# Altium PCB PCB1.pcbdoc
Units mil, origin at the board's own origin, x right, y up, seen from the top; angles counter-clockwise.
Board outline 4319.97 x 3807.09 mil, 2 copper layers (Top Layer, Bottom Layer); 37 components, 97 nets, 317 pads, 179 vias.
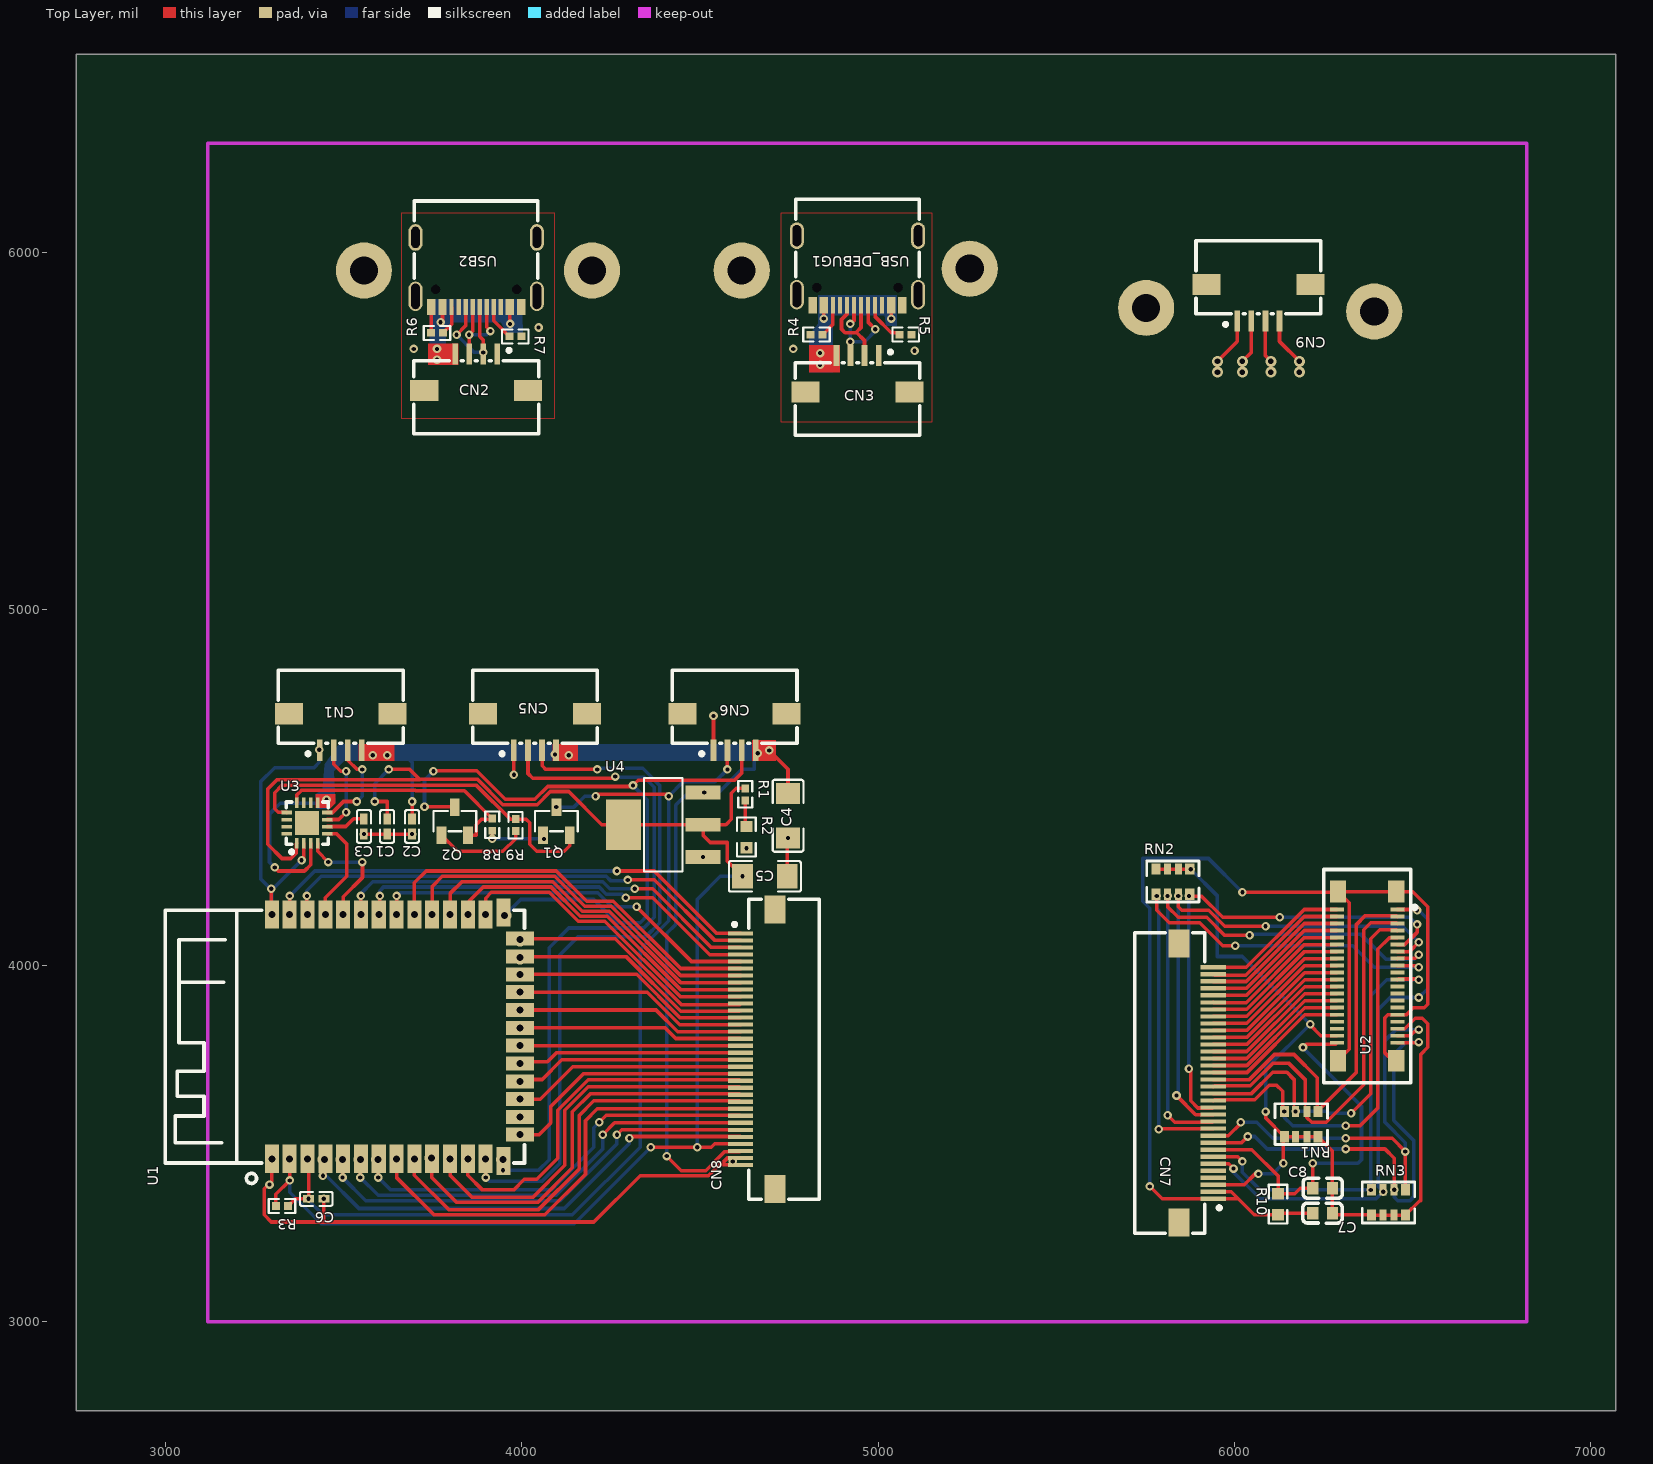
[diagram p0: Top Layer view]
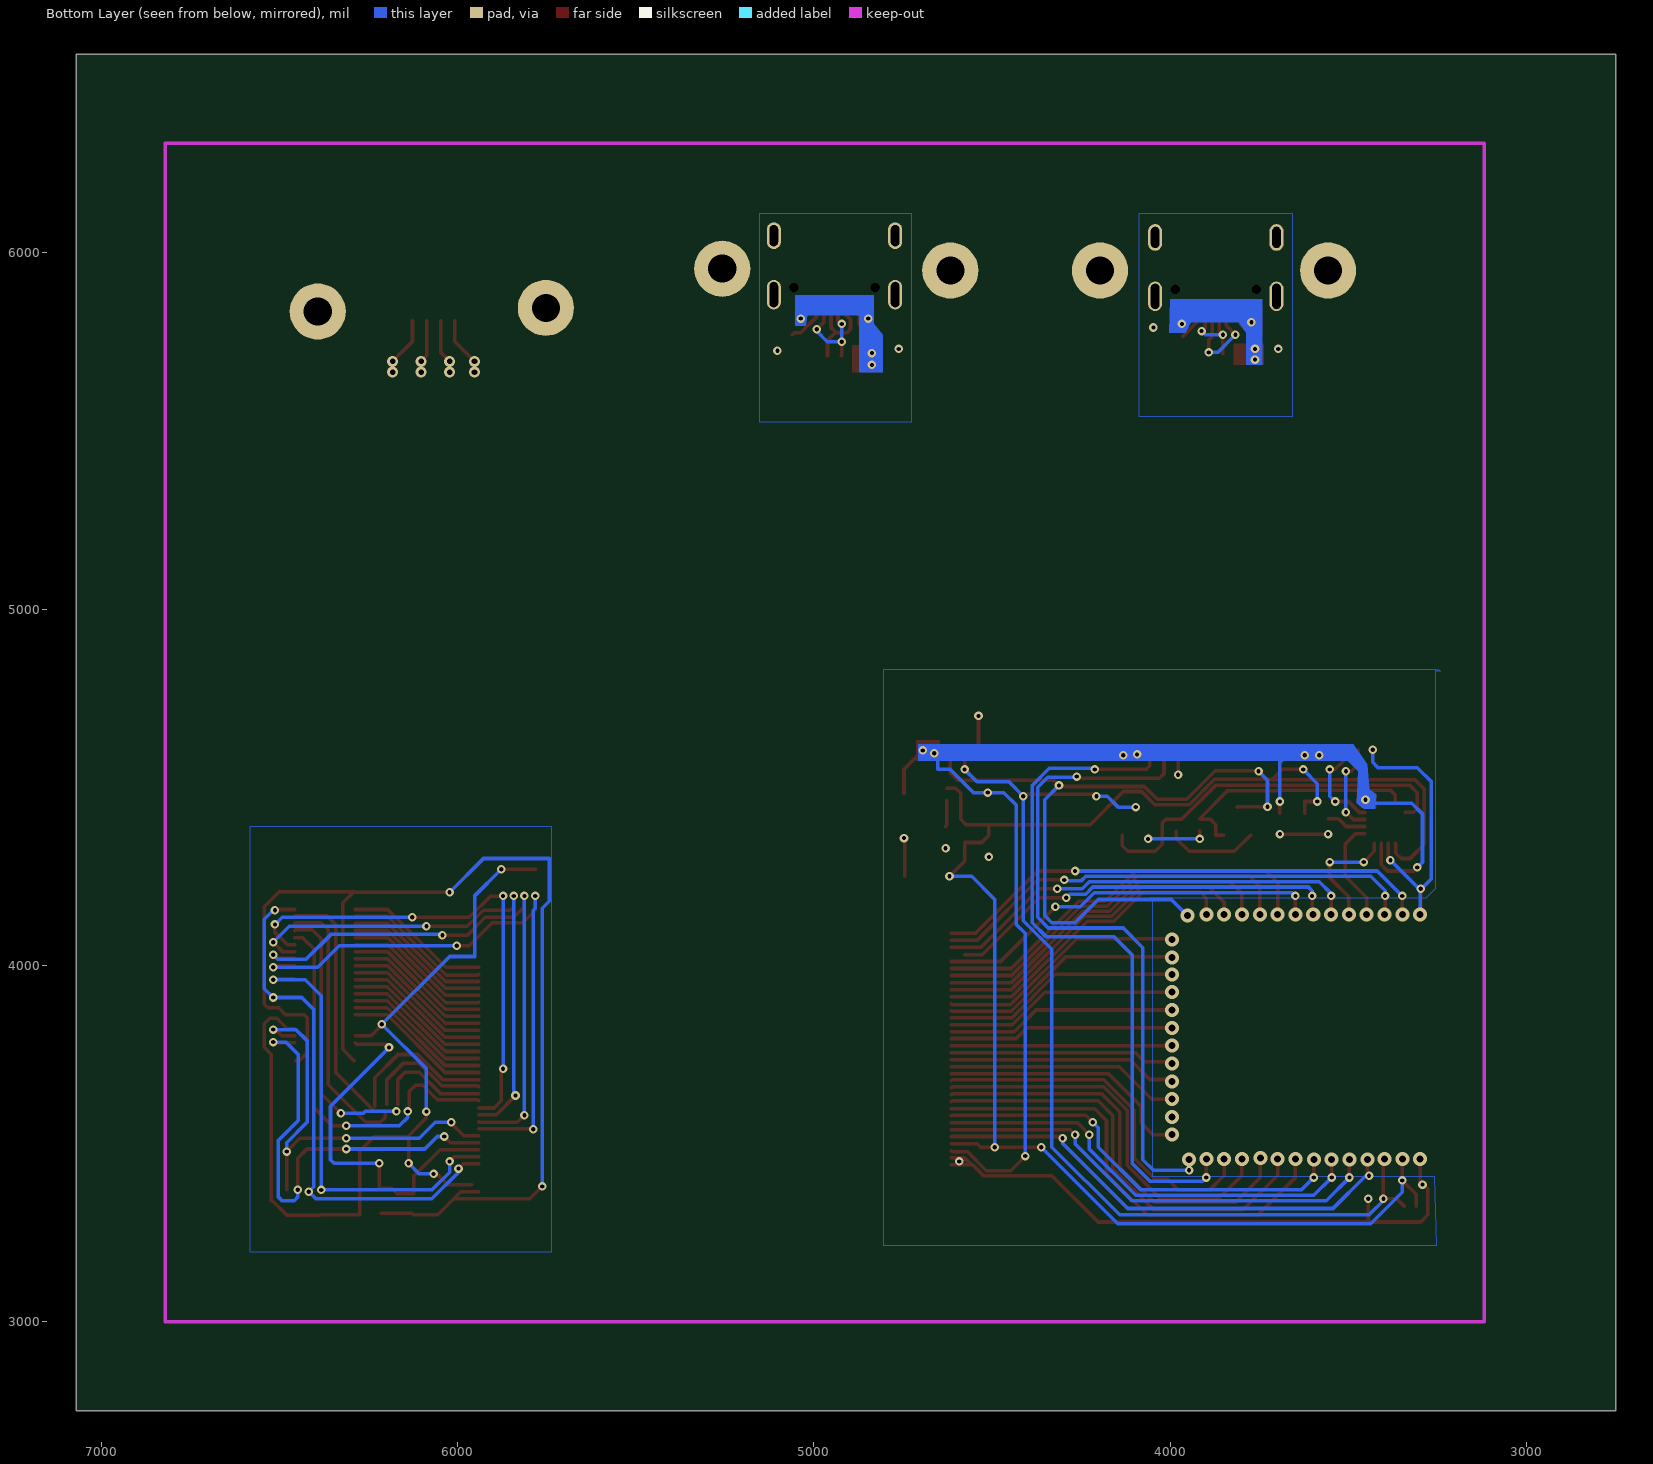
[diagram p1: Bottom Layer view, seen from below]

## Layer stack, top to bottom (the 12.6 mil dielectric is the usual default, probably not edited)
Top Layer: signal copper (thickness not stored)
Dielectric: dielectric 12.6, FR-4, Dk 4.8
Bottom Layer: signal copper (thickness not stored)

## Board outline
7069.97,2750 2750,2750 2750,6557.09 7069.97,6557.09

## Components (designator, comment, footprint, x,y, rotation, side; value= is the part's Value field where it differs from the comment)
C1 "CL05A105KA5NQNC" C0402 3622.3,4390.24 r270 top
C2 "CL05A105KA5NQNC" C0402 3692.3,4390.24 r90 top
C3 "CL05B104KO5NNNC" C0402 3557.3,4390.24 r90 top
C4 "CL31A106KBHNNNE" C1206 4747.3,4420.24 r90 top
C5 "C3216X5R1V226MTJ00E" C1206 4682.3,4250.24 r180 top
C6 "CL05A105KP5NNNC" C0402 3423.46,3345.24 r180 top
C7 "CL10A225KO8NNNC" C0603 6247.3,3375.24 r180 top
C8 "0603B104K500NT" C0603 6247.3,3305.24 r0 top
CN1 "KH-FG1.0-H2.0-4PIN" FPC-SMD_KH-FG1.0-H2.0-4PIN 3492.3,4655.24 r180 top
CN2 "KH-FG1.0-H2.0-4PIN" FPC-SMD_KH-FG1.0-H2.0-4PIN 3872.3,5665.24 r0 top
CN3 "KH-FG1.0-H2.0-4PIN" FPC-SMD_KH-FG1.0-H2.0-4PIN 4942.3,5660.24 r0 top
CN5 "KH-FG1.0-H2.0-4PIN" FPC-SMD_KH-FG1.0-H2.0-4PIN 4037.3,4655.24 r180 top
CN6 "KH-FG1.0-H2.0-4PIN" FPC-SMD_KH-FG1.0-H2.0-4PIN 4597.3,4655.24 r180 top
CN7 "KH-FG0.5-H2.0-34PIN" FPC-SMD_KH-FG0.5-H2.0-34PIN 5892.3,3670.24 r270 top
CN8 "KH-FG0.5-H2.0-34PIN" FPC-SMD_KH-FG0.5-H2.0-34PIN 4662.3,3765.24 r90 top
CN9 "KH-FG1.0-H2.0-4PIN" FPC-SMD_KH-FG1.0-H2.0-4PIN 6067.3,5860.24 r180 top
Q1 "SS8050G-Y1" SOT-23-3_L2.9-W1.3-P1.90-LS2.4-BR 4097.3,4405.24 r270 top
Q2 "SS8050G-Y1" SOT-23-3_L2.9-W1.3-P1.90-LS2.4-BR 3812.3,4405.24 r270 top
R1 "0402WGF6800TCE" R0402 4627.3,4480.24 r270 top
R2 "0603WAF0000T5E" R0603 4630.56,4360.43 r270 top
R3 "0402WGF1002TCE" R0402 3327.3,3325.24 r180 top
R4 "0402WGF5101TCE" R0402 4827.3,5770.24 r180 top
R5 "0402WGF5101TCE" R0402 5077.3,5770.24 r0 top
R6 "0402WGF5101TCE" R0402 3762.3,5775.24 r180 top
R7 "0402WGF5101TCE" R0402 3982.3,5765.24 r0 top
R8 "0402WGF1002TCE" R0402 3917.3,4395.24 r270 top
R9 "0402WGF1002TCE" R0402 3983.06,4393.97 r270 top
R10 "0603WAF1003T5E" R0603 6122.3,3330.24 r270 top
RN1 "4D03WGJ0472T5E" RES-ARRAY-SMD_0603-8P-L3.2-W1.6-BL 6187.3,3555.24 r180 top
RN2 "4D03WGJ0472T5E" RES-ARRAY-SMD_0603-8P-L3.2-W1.6-BL 5827.3,4235.24 r0 top
RN3 "4D03WGJ0472T5E" RES-ARRAY-SMD_0603-8P-L3.2-W1.6-BL 6432.3,3335.24 r180 top
U1 "ESP-S3-32S" WIFIM-SMD_40P-L25.5-W18.0-P1.27-TL 3647.3,3800.24 r90 top
U2 "AA01B-S040VA1" CONN-SMD_AA01B-S040VA1 6372.3,3970.24 r90 top
U3 "CH343P" TQFN-16_L3.0-W3.0-P0.50-BL-EP1.7 3397.94,4399.85 r0 top
U4 "AMS1117-3.3_C347222" SOT-223-4_L6.5-W3.5-P2.30-LS7.0-BR 4397.3,4395.24 r0 top
USB2 "TYPEC-304J-BCP16" USB-C-SMD_TYPEC-304J-BCP16 3872.3,5945.24 r180 top
USB_DEBUG1 "TYPEC-304J-BCP16" USB-C-SMD_TYPEC-304J-BCP16 4942.3,5950.24 r180 top

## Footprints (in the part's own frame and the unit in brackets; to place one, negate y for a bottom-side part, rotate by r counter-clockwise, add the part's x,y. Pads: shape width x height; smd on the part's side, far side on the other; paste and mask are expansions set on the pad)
C0402 [mm]
  rect 0.79x0.54 smd paste-100 mask+0.051: 1(-0.545,0) 2(0.545,0)
  silkscreen extent -1.17,-0.5 1.17,0.5
C0603 [mm]
  rect 0.8x0.9 smd paste+0 mask+0.051: 1(-0.7,0) 2(0.7,0)
  silkscreen extent -1.41,-0.71 1.39,0.72
C1206 [mm]
  rect 1.485x1.728 smd paste-100 mask+0.051: 1(-1.593,0) 2(1.593,0)
  silkscreen extent -2.56,-1.09 2.56,1.09
CONN-SMD_AA01B-S040VA1 [mm]
  rect 0.28x1 smd paste+0 mask+0.051: 1(4.75,-2.158) 2(4.75,2.158) 3(4.25,-2.158) 4(4.25,2.158) 5(3.75,-2.158) 6(3.75,2.158) 7(3.25,-2.158) 8(3.25,2.158) 9(2.75,-2.158) 10(2.75,2.158) 11(2.25,-2.158) 12(2.25,2.158) 13(1.75,-2.158) 14(1.75,2.158) 15(1.25,-2.158) 16(1.25,2.158) 17(0.75,-2.158) 18(0.75,2.158) 19(0.249,-2.158) 20(0.249,2.158) 21(-0.25,-2.158) 22(-0.25,2.158) 23(-0.75,-2.158) 24(-0.75,2.158) 25(-1.25,-2.158) 26(-1.25,2.158) 27(-1.75,-2.158) 28(-1.75,2.158) 29(-2.25,-2.158) 30(-2.25,2.158) 31(-2.75,-2.158) 32(-2.75,2.158) 33(-3.25,-2.158) 34(-3.25,2.158) 35(-3.75,-2.158) 36(-3.75,2.158) 37(-4.25,-2.158) 38(-4.25,2.158) 39(-4.75,-2.158) 40(-4.75,2.158)
  rect 1.55x1.15 smd paste+0 mask+0.051: 41(6.025,2.075) 42(6.025,-2.075) 43(-6.025,2.075) 44(-6.025,-2.075)
  silkscreen extent -7.6,-3.54 7.6,3.1
FPC-SMD_KH-FG0.5-H2.0-34PIN [mm]
  rect 0.3x1.8 smd paste+0 mask+0.051: 1(8.25,1.225) 2(7.75,1.225) 3(7.25,1.225) 4(6.75,1.225) 5(6.25,1.225) 6(5.75,1.225) 7(5.25,1.225) 8(4.75,1.225) 9(4.25,1.225) 10(3.75,1.225) 11(3.25,1.225) 12(2.75,1.225) 13(2.25,1.225) 14(1.75,1.225) 15(1.25,1.225) 16(0.75,1.225) 17(0.25,1.225) 18(-0.25,1.225) 19(-0.75,1.225) 20(-1.25,1.225) 21(-1.75,1.225) 22(-2.25,1.225) 23(-2.75,1.225) 24(-3.25,1.225) 25(-3.75,1.225) 26(-4.25,1.225) 27(-4.75,1.225) 28(-5.25,1.225) 29(-5.75,1.225) 30(-6.25,1.225) 31(-6.75,1.225) 32(-7.25,1.225) 33(-7.75,1.225) 34(-8.25,1.225)
  rect 2x1.5 smd paste+0 mask+0.051: 35(-9.95,-1.225) 36(9.95,-1.225)
  silkscreen extent -10.7,-4.38 10.7,1.78
FPC-SMD_KH-FG1.0-H2.0-4PIN [mm]
  rect 0.4x1.5 smd paste+0 mask+0.05: 1(1.5,1.3) 2(0.5,1.3) 3(-0.5,1.3) 4(-1.5,1.3)
  rect 2x1.5 smd paste+0 mask+0.05: 5(-3.7,-1.3) 6(3.7,-1.3)
  silkscreen extent -4.45,-4.39 4.45,1.68
R0402 [mm]
  rect 0.566x0.54 smd paste-100 mask+0.051: 1(-0.433,0) 2(0.433,0)
  silkscreen extent -0.94,-0.5 0.94,0.5
R0603 [mil]
  rect 31.75x34.02 smd paste-3937.01 mask+2: 1(-29.66,0) 2(29.66,0)
  silkscreen extent -55,-26 55,26
RES-ARRAY-SMD_0603-8P-L3.2-W1.6-BL [mm]
  rect 0.65x0.8 smd paste+0 mask+0.051: 1(-1.2,-0.9) 4(1.2,-0.9) 5(1.2,0.9) 8(-1.2,0.9)
  rect 0.5x0.8 smd paste+0 mask+0.051: 2(-0.4,-0.9) 3(0.4,-0.9) 6(0.4,0.9) 7(-0.4,0.9)
  silkscreen extent -1.87,-1.45 1.87,1.47
SOT-23-3_L2.9-W1.3-P1.90-LS2.4-BR [mm]
  rect 1.25x0.7 smd paste+0 mask+0.051: 1(1,-0.95) 2(1,0.95) 3(-1,0)
  silkscreen extent -0.73,-1.53 0.73,1.53
SOT-223-4_L6.5-W3.5-P2.30-LS7.0-BR [mm]
  rect 2.47x0.98 smd paste+0 mask+0.051: 1(2.835,-2.3) 2(2.835,0) 3(2.835,2.3)
  rect 2.47x3.6 smd paste+0 mask+0.051: 4(-2.835,0)
  silkscreen extent -1.37,-3.33 1.37,3.33
TQFN-16_L3.0-W3.0-P0.50-BL-EP1.7 [mm]
  rect 0.25x0.75 smd paste-100 mask+0.051: 1(-0.748,-1.45) 2(-0.249,-1.45) 3(0.252,-1.45) 4(0.751,-1.45) 9(0.75,1.45) 10(0.25,1.45) 11(-0.25,1.45) 12(-0.749,1.45)
  rect 0.75x0.25 smd paste-100 mask+0.051: 5(1.45,-0.75) 6(1.45,-0.25) 7(1.45,0.25) 8(1.45,0.75) 13(-1.45,0.75) 14(-1.45,0.25) 15(-1.45,-0.25) 16(-1.45,-0.75)
  rect 1.7x1.7 smd paste-100 mask+0.051: 17(0,0)
  silkscreen extent -1.5,-2.17 1.5,1.5
USB-C-SMD_TYPEC-304J-BCP16 [mm]
  oval 1x2.1 hole 0.6 slot 1.8 at 90 deg paste+0 mask+0.051: 13(-4.325,1.719) 14(4.325,1.719)
  oval 1x1.9 hole 0.6 slot 1.5 at 90 deg paste+0 mask+0.051: 15(-4.325,-2.481) 16(4.325,-2.481)
  rect 0.6x1.15 smd paste-100 mask+0.051: A1B12(-3.2,2.481) A4B9(-2.4,2.481) B1A12(3.2,2.481) B4A9(2.4,2.481)
  rect 0.3x1.15 smd paste-100 mask+0.051: A5(-1.25,2.481) A6(-0.25,2.481) A7(0.25,2.481) A8(1.25,2.481) B5(1.75,2.481) B6(0.75,2.481) B7(-0.75,2.481) B8(-1.75,2.481)
  Multi-Layer board cut-out: 2.565,1.219 2.597,1.078 2.688,0.965 2.818,0.902 2.962,0.902 3.093,0.965 3.183,1.078 3.215,1.219 3.215,1.219 3.183,1.36 3.093,1.473 2.962,1.536 2.818,1.536 2.688,1.473 2.597,1.36 2.565,1.219
  Multi-Layer board cut-out: -3.215,1.219 -3.183,1.078 -3.093,0.965 -2.962,0.902 -2.818,0.902 -2.687,0.965 -2.597,1.078 -2.565,1.219 -2.565,1.219 -2.597,1.36 -2.687,1.473 -2.818,1.536 -2.962,1.536 -3.093,1.473 -3.183,1.36 -3.215,1.219
  silkscreen extent -4.4,-5.08 4.4,0.44
WIFIM-SMD_40P-L25.5-W18.0-P1.27-TL [mm]
  rect 2x1 smd paste+0 mask+0.051: 1(-8.7,8.849) 2(-8.7,7.579) 3(-8.7,6.309) 4(-8.7,5.039) 5(-8.7,3.769) 6(-8.7,2.499) 7(-8.7,1.229) 8(-8.7,-0.041) 9(-8.7,-1.311) 10(-8.7,-2.581) 11(-8.7,-3.851) 12(-8.7,-5.121) 13(-8.7,-6.391) 14(-8.85,-7.661) 27(8.85,-7.661) 28(8.7,-6.391) 29(8.7,-5.121) 30(8.7,-3.851) 31(8.7,-2.581) 32(8.7,-1.311) 33(8.7,-0.041) 34(8.7,1.229) 35(8.7,2.499) 36(8.7,3.769) 37(8.7,5.039) 38(8.7,6.309) 39(8.7,7.579) 40(8.7,8.849)
  rect 1x2 smd paste+0 mask+0.051: 15(-6.986,-8.849) 16(-5.716,-8.849) 17(-4.446,-8.849) 18(-3.176,-8.849) 19(-1.906,-8.849) 20(-0.636,-8.849) 21(0.634,-8.849) 22(1.904,-8.849) 23(3.174,-8.849) 24(4.444,-8.849) 25(5.714,-8.849) 26(6.984,-8.849)
  silkscreen extent -10.46,-9.16 9,16.44

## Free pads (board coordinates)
  round 157.48 hole 78.74 paste+0 mask+2: 1(3557.3,5950.24) 1(4197.3,5950.24) 1(4617.3,5950.24) 1(5257.3,5955.24) 1(5752.3,5845.24) 1(6392.3,5835.24)

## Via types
v1: diameter 24.02, hole 12.01, Top Layer to Bottom Layer, 131 vias
v2: diameter 39.37, hole 19.68, Top Layer to Bottom Layer, 40 vias
v3: diameter 31.5, hole 15.75, Top Layer to Bottom Layer, 8 vias

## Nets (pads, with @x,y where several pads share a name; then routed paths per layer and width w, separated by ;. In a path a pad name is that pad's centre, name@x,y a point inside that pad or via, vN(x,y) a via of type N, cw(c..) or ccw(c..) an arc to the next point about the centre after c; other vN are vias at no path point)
$1N3962: R1.2 R2.1 | length 74.5
  Top Layer w10: R1.2 4627.3,4393.35 R2.1
$1N4727: R5.1 USB_DEBUG1.A5 | length 121.3
  Top Layer w10: USB_DEBUG1.A5 4991.5,5821.03 5037.3,5775.24 5055.26,5775.24 R5.1
$1N4742: R4.1 USB_DEBUG1.B5 | length 94.3
  Top Layer w10: R4.1 4873.4,5799.3 USB_DEBUG1.B5
$1N5488: R7.1 USB2.A5 | length 100.4
  Top Layer w10: USB2.A5 3921.5,5808.99 R7.1
$1N5500: R6.1 USB2.B5 | length 82.3
  Top Layer w10: R6.1 3803.4,5799.3 USB2.B5
$1N6780: Q2.1 R9.2 | length 262.8
  Top Layer w10: Q2.1 3820.53,4320.24 3947.3,4320.24 3983.06,4356.01 R9.2
$1N6783: Q1.1 R8.2 | length 179.6
  Top Layer w10: v1(3917.3,4355.24) R8.2 ; Q1.1 4062.3,4363.47 v1(4062.3,4355.24)
  Bottom Layer w10: v1(3917.3,4355.24) v1(4062.3,4355.24)
$1N7702: CN7.34 U2.2 | length 414
  Top Layer w10: CN7.34 6033.46,3995.04 6195.66,4157.24 U2.2
$1N7716: CN7.33 U2.4 | length 415.8
  Top Layer w10: CN7.33 5942.72,3973.15 6031.37,3973.15 6195.77,4137.55 U2.4
$1N7875: CN7.32 U2.6 | length 414.4
  Top Layer w10: CN7.32 5940.95,3955.24 6033.26,3955.24 6195.88,4117.86 U2.6
$1N7880: CN7.31 U2.8 | length 414
  Top Layer w10: CN7.31 6033.8,3935.98 6196,4098.18 U2.8
$1N7885: CN7.30 U2.10 | length 414
  Top Layer w10: CN7.30 6033.91,3916.3 6196.11,4078.49 U2.10
$1N7890: CN7.29 U2.12 | length 415.1
  Top Layer w10: CN7.29 5941.89,3895.24 6032.65,3895.24 6196.22,4058.81 U2.12
$1N7895: CN7.28 U2.14 | length 414
  Top Layer w10: CN7.28 6034.14,3876.93 6196.33,4039.12 U2.14
$1N7900: CN7.27 U2.16 | length 414
  Top Layer w10: CN7.27 6034.25,3857.24 6196.45,4019.44 U2.16
$1N7909: CN7.26 U2.18 | length 414
  Top Layer w10: CN7.26 6034.37,3837.56 6196.56,3999.75 U2.18
$1N7914: CN7.25 U2.20 | length 414
  Top Layer w10: CN7.25 6034.48,3817.87 6196.67,3980.06 U2.20
$1N7919: CN7.24 U2.22 | length 414
  Top Layer w10: CN7.24 6034.6,3798.19 6196.79,3960.38 U2.22
$1N7924: CN7.23 U2.24 | length 414
  Top Layer w10: CN7.23 6034.71,3778.5 6196.91,3940.7 U2.24
$1N7938: CN7.22 U2.26 | length 414
  Top Layer w10: CN7.22 6034.83,3758.82 6197.02,3921.01 U2.26
$1N7945: CN7.21 U2.28 | length 414
  Top Layer w10: CN7.21 6034.94,3739.13 6197.14,3901.33 U2.28
$1N7952: CN7.20 U2.30 | length 414
  Top Layer w10: CN7.20 6035.05,3719.45 6197.25,3881.64 U2.30
$1N7980: CN7.19 U2.32 | length 414
  Top Layer w10: CN7.19 6035.16,3699.76 6197.36,3861.96 U2.32
$1N11911: CN7.18 RN1.1 U2.3 | length 1122.9
  Top Layer w10: CN7.18 6042.14,3680.08 6112.3,3750.24 6167.3,3750.24 6232.3,3685.24 RN1.1@6232.3,3605.67 ; RN1.1 6234.53,3592.48 6342.3,3700.24 6342.3,4115.24 6367.3,4140.24 6454.56,4140.24 U2.3
$1N11924: CN7.17 RN1.2 U2.5 | length 1137.4
  Top Layer w10: CN7.17 5942.73,3662.6 6044.65,3662.6 6107.3,3725.24 6153.05,3725.24 6198.05,3680.24 6198.05,3610.67 ; RN1.2 6203.05,3573.66 6216.47,3560.24 6257.71,3560.24 6362.71,3665.24 6362.71,4100.65 6382.3,4120.24 6454.87,4120.24 U2.5
$1N11961: CN7.15 RN1.4 U2.9 | length 1084.2
  Top Layer w10: CN7.15 5943.32,3623.82 6056.97,3623.82 6097.3,3664.14 6117.91,3664.14 6135.06,3647 RN1.4@6135.06,3605.67 ; v1(6312.3,3550.24) 6352.3,3550.24 6402.3,3600.24 6402.3,4045.24 6435.55,4078.49 U2.9
  Bottom Layer w10: v1(6140.06,3590.67) 6140.06,3573.66 6163.48,3550.24 v1(6312.3,3550.24)
$1N12399: CN7.16 RN1.3 U2.7 | length 1086.4
  Top Layer w10: CN7.16 6047.77,3640.71 6107.3,3700.24 6147.22,3700.24 6167.22,3680.24 6167.22,3611.34 6166.55,3610.67 ; v1(6327.3,3585.24) 6382.3,3640.24 6382.3,4075.24 6407.3,4100.24 6455.19,4100.24 U2.7
  Bottom Layer w10: v1(6171.55,3590.67) 6258.55,3590.67 6263.99,3585.24 v1(6327.3,3585.24)
$1N12461: CN7.14 RN2.4 U2.11 | length 1416.3
  Top Layer w10: v1(5872.3,3710.24) 5877.3,3705.24 5877.3,3620.24 5897.3,3600.24 5939.42,3600.24 CN7.14 ; RN2.4 5874.53,4194.8 5907.73,4194.8 5967.3,4135.24 v1(6127.3,4135.24) ; U2.11 6478.3,4058.81 6512.3,4092.81 v1(6512.3,4115.24)
  Bottom Layer w10: v1(5872.3,3710.24) v1(5872.3,4195.24) ; v1(6127.3,4135.24) 6492.3,4135.24 v1(6512.3,4115.24)
$1N12469: CN7.11 RN2.1 U2.17 | length 1714.3
  Top Layer w10: v1(5782.3,4195.24) 5782.3,4155.24 5817.3,4120.24 5902.3,4120.24 5967.3,4055.24 v1(6002.3,4055.24) ; v1(5787.3,3540.24) 5789.35,3542.29 CN7.11 ; U2.17 6512.78,3999.75 v1(6517.3,3995.24)
  Bottom Layer w10: v1(5782.3,4195.24) 5782.3,4160.24 5787.3,4155.24 v1(5787.3,3540.24) ; v1(6002.3,4055.24) 6332.3,4055.24 6392.3,3995.24 v1(6517.3,3995.24)
$1N12482: CN7.13 RN2.3 U2.13 | length 1504.8
  Top Layer w10: v1(5837.3,3635.24) 5890.89,3581.65 CN7.13 ; v1(5842.3,4195.24) 5842.3,4165.24 5852.3,4155.24 5927.5,4155.24 5972.5,4110.24 v1(6087.3,4110.24) ; U2.13 6491.18,4039.12 v1(6517.3,4065.24)
  Bottom Layer w10: v1(5837.3,3635.24) 5842.3,3640.24 v1(5842.3,4195.24) ; v1(6087.3,4110.24) 6472.3,4110.24 v1(6517.3,4065.24)
$1N12495: CN7.12 RN2.2 U2.15 | length 1625
  Top Layer w10: RN2.2 5812.3,4199.05 v1(5812.3,4195.24) 5812.3,4165.24 5842.3,4135.24 5921.92,4135.24 5971.92,4085.24 v1(6042.3,4085.24) ; v1(5812.3,3580.24) 5832.3,3560.24 5938.79,3560.24 CN7.12 ; U2.15 6458.04,4020.24 6507.3,4020.24 v1(6517.3,4030.24)
  Bottom Layer w10: v1(5812.3,3580.24) v1(5812.3,4195.24) ; v1(6042.3,4085.24) 6044.3,4087.24 6355.29,4087.24 6425.29,4017.24 6504.3,4017.24 v1(6517.3,4030.24)
$1N16399: CN9.1 | length 167
  Top Layer w10: v3(5952.3,5665.24) v3(5952.3,5695.24) 6008.24,5751.18 CN9.1
$1N16400: CN9.4 | length 167
  Top Layer w10: CN9.4 6126.35,5751.18 v3(6182.3,5695.24) v3(6182.3,5665.24)
$1N16402: CN9.2 | length 154.3
  Top Layer w10: v3(6022.3,5665.24) v3(6022.3,5695.24) 6047.61,5720.55 CN9.2
$1N16404: CN9.3 | length 150.2
  Top Layer w10: CN9.3 6086.98,5710.55 v3(6102.3,5695.24) v3(6102.3,5665.24)
CHIP_PU: C6.2 CN6.2 Q1.3 R3.1 U1.3 | length 2811.9
  Top Layer w10: R3.1 3364.34,3345.24 v1(3402,3345.24) 3402,3454.63 v2(3398.92,3457.72) ; v1(4207.3,4475.24) 4212.3,4480.24 4407.3,4480.24 v1(4412.3,4475.24) ; v1(4577.3,4550.24) 4577.3,4603.74 CN6.2
  Bottom Layer w10: v1@3397.3,3345.24 3442.3,3300.24 4142.3,3300.24 4332.3,3490.24 4332.3,4045.24 4412.3,4125.24 4412.3,4475.06 4452.47,4515.24 4542.3,4515.24 v1(4577.3,4550.24) ; v1(4097.3,4444.61) 4146.66,4444.61 4177.3,4475.24 v1(4207.3,4475.24)
D1+: CN2.2 USB2.A6 USB2.B6 | length 319
  Top Layer w10: v1(3817.3,5770.24) 3842.77,5795.71 USB2.B6 ; USB2.A6 3882.3,5847.38 3882.3,5765.24 3892.3,5755.24 3892.3,5716.73 CN2.2
  Bottom Layer w10: v1(3817.3,5770.24) 3867.3,5720.24 v1(3892.3,5720.24)
D1-: CN2.3 USB2.A7 USB2.B7 | length 271.3
  Top Layer w10: CN2.3 3852.3,5716.73 v1(3852.3,5770.24) 3862.3,5780.24 3862.3,5847.39 USB2.A7 ; USB2.B7 3901.82,5790.71 v1(3912.3,5780.24)
  Bottom Layer w10: v1(3852.3,5770.24) 3902.3,5770.24 v1(3912.3,5780.24)
D2+: CN3.2 USB_DEBUG1.A6 USB_DEBUG1.B6 | length 275.4
  Top Layer w10: USB_DEBUG1.B6 4912.77,5828.16 4897.3,5812.68 4897.3,5785.89 4907.3,5775.89 4937.95,5775.89 4938.95,5776.89 ; USB_DEBUG1.A6 4952.13,5790.07 4938.95,5776.89 ; CN3.2 4961.98,5753.87 4938.95,5776.89
D2-: CN3.3 USB_DEBUG1.A7 USB_DEBUG1.B7 | length 309.2
  Top Layer w10: v1(4922.3,5750.24) 4922.3,5711.73 CN3.3 ; v1(4922.3,5800.24) 4923.15,5800.24 4932.45,5809.53 USB_DEBUG1.A7 ; USB_DEBUG1.B7 4971.82,5805.71 v1(4992.3,5785.24)
  Bottom Layer w10: v1(4922.3,5800.24) v1(4922.3,5750.24) 4962.3,5750.24 4992.3,5780.24 v1(4992.3,5785.24)
D3+: CN1.2 U3.7 | length 257.7
  Top Layer w10: U3.7 3486.76,4409.7 v1(3507.3,4430.24) ; CN1.2 3472.61,4564.92 3492.3,4545.24 v1(3507.3,4545.24)
  Bottom Layer w10: v1(3507.3,4430.24) v1(3507.3,4545.24)
D3-: CN1.3 U3.8 | length 270.1
  Top Layer w10: U3.8 3469.17,4429.38 3500.03,4460.24 v1(3537.3,4460.24) ; CN1.3 3511.98,4576.41 3538.15,4550.24 v1(3552.3,4550.24)
  Bottom Layer w10: v1(3537.3,4460.24) 3552.3,4475.24 v1(3552.3,4550.24)
D+: CN5.2 U1.14 | length 1902.7
  Top Layer w10: v1(3947.3,3425.24) v2(3947.3,3455.24) ; CN5.2 4017.61,4538.76 4031.14,4525.24 4257.3,4525.24 v1(4262.3,4530.24)
  Bottom Layer w10: v1(3947.3,3425.24) 4047.3,3425.24 4077.3,3455.24 4077.3,4050.24 4132.3,4105.24 4342.3,4105.24 4372.3,4135.24 4372.3,4500.24 4344.3,4528.23 4264.3,4528.23 v1(4262.3,4530.24)
D-: CN5.3 U1.13 | length 1972.2
  Top Layer w10: v1(3898.92,3405.24) v2(3898.92,3457.72) ; CN5.3 4056.98,4594.49 4057.3,4594.18 4057.3,4560.24 4067.3,4550.24 v1(4212.3,4550.24)
  Bottom Layer w10: v1(3898.92,3405.24) 3908.92,3395.24 4057.3,3395.24 4107.3,3445.24 4107.3,4030.24 4157.3,4080.24 4347.3,4080.24 4387.3,4120.24 4387.3,4505.24 4339.3,4553.23 4215.29,4553.23 v1(4212.3,4550.24)
DTR: Q2.2 R8.1 U3.12 | length 712.5
  Top Layer w10: U3.12 3368.45,4478.7 3380.97,4491.22 3701.31,4491.22 3702.3,4490.24 3839.34,4490.24 R8.1 3915.26,4410.24 3887.3,4410.24 3872.3,4395.24 3872.3,4365.87 Q2.2
GND: C1.2 C2.1 C3.1 C4.1 C5.1 C6.1 CN1.1 CN5.1 CN6.1 CN8.33 CN8.34 R2.2 U1.1 U1.40 U3.2 U3.17 U4.1 | length 2965.4
  Top Layer w10: v1(3297.3,4215.24) 3297.3,4144.38 v2(3298.92,4142.76) ; v2(3298.92,3457.72) 3298.92,3395.24 3277.3,3373.62 3277.3,3300.24 3297.3,3280.24 3445.71,3280.24 ; v1(3382.3,4295.24) 3388.16,4301.1 U3.2 ; v1(3444.92,3345.24) 3444.92,3281.03 3445.71,3280.24 ; v1(3557.3,4368.78) C1.2 v1(3692.3,4368.78) ; v1(3978.24,4535.24) CN5.1 ; CN6.1 v1(4538.24,4700.24) ; CN8.34 4557.6,3440.44 ; CN8.33 4577.3,3460.13 4557.6,3440.44 ; C5.1 4744.99,4355.24 v1(4747.3,4357.54) ; 3445.71,3280.24 4202.3,3280.24 4332.49,3410.44 4524.07,3410.44 4554.07,3440.44 4557.6,3440.44
  Bottom Layer w10: v2(3298.92,4142.76) v1@3298.92,4211.86 ; v1(3382.3,4295.24) v1@3298.92,4211.86 ; v1(3432.3,4605.24) 3432.3,4570.24 3417.3,4555.24 3307.3,4555.24 3267.3,4515.24 3267.3,4243.48 v1@3298.92,4211.86
  other v1: 3292.3,3385.24 4592.3,3450.24 4508.9,4304.69 4630.56,4329.13
GND_11: C8.1 CN7.1 CN7.2 R10.2 U2.31 U2.41 U2.42 U2.43 U2.44 | length 3400.9
  Top Layer w10: v1(5762.3,3380.24) 5797.1,3345.44 CN7.1 6010.52,3345.44 ; CN7.2 5990.84,3365.12 6010.52,3345.44 ; v1(6022.3,4205.24) 6288.39,4205.24 U2.41 ; C8.1@6214.06,3305.24 6126.95,3305.24 R10.2 6055.38,3300.58 6010.52,3345.44 ; U2.43 6322.3,3764.72 6322.3,4175.76 U2.41 ; U2.44 6443.98,3733.03 6422.3,3754.72 6422.3,3853.69 6430.56,3861.96 U2.31 6482.85,3861.96 6501.94,3881.05 6532.3,3881.05 6542.3,3891.05 6542.3,4165.24 6500.08,4207.45 U2.42 U2.41
  Bottom Layer w10: v1(5762.3,3380.24) 5762.3,4160.24 5742.3,4180.24 5742.3,4300.24 5927.3,4300.24 v1(6022.3,4205.24)
GND_DEBUG: CN3.1 R4.2 R5.2 USB_DEBUG1.13 USB_DEBUG1.14 USB_DEBUG1.15 USB_DEBUG1.16 USB_DEBUG1.A1B12 USB_DEBUG1.B1A12
  other v1: 5102.3,5725.24 4762.3,5730.24
GND_USB: CN2.1 R6.2 R7.2 USB2.13 USB2.14 USB2.15 USB2.16 USB2.A1B12 USB2.B1A12 | length 72.7
  Top Layer w10: R6.2 3746.31,5776.29 USB2.B1A12
  other v1: 3697.3,5730.24 4047.3,5790.24
GPIO0(BOOT): CN6.3 Q2.3 U1.27 | length 2023.9
  Top Layer w10: v1(3727.3,4445.24) 3811.66,4445.24 Q2.3 ; v1(3752.3,4545.24) 3753.3,4546.24 3873.91,4546.24 3953.91,4466.24 4036.66,4466.24 4072.66,4502.24 4309.3,4502.24 v1(4312.3,4505.24) 4327.3,4520.24 4597.3,4520.24 4616.98,4539.92 CN6.3
  Bottom Layer w10: v1(3727.3,4445.24) 3727.3,4520.24 v1(3752.3,4545.24) ; v2(3952.3,4140.24) 3997.3,4185.24 4202.3,4185.24 4267.3,4120.24 4332.3,4120.24 4352.3,4140.24 4352.3,4465.24 v1(4312.3,4505.24)
HOTKEY: CN7.6 RN3.3 U2.1 | length 1508.8
  Top Layer w10: CN7.6 5983.68,3443.86 v1(5997.3,3430.24) ; RN3.3 6417.3,3369.92 v1(6417.3,3365.24) ; U2.1 6510.29,4157.24 v1(6512.3,4155.24)
  Bottom Layer w10: v1(5997.3,3430.24) 5997.3,3420.24 6072.3,3345.24 6397.3,3345.24 v1(6417.3,3365.24) 6403.57,3378.97 6403.57,3876.51 6437.3,3910.24 v1(6517.3,3910.24) 6542.3,3935.24 6542.3,4130.24 6517.3,4155.24 v1(6512.3,4155.24)
IO1: CN8.1 U1.39 | length 1421.7
  Top Layer w10: v2(3348.92,4142.76) v1(3348.92,4195.24) ; v1(4267.3,4265.24) 4372.3,4265.24 4547.49,4090.04 CN8.1
  Bottom Layer w10: v1(3348.92,4195.24) 3418.92,4265.24 v1@4269.81,4265.24
IO2: CN8.2 U1.38 | length 1377.5
  Top Layer w10: v1(3397.3,4195.24) 3397.3,4144.38 v2(3398.92,4142.76) ; v1(4297.3,4240.24) 4372.3,4240.24 4542.18,4070.36 CN8.2
  Bottom Layer w10: v1(3397.3,4195.24) 3397.3,4210.24 3437.3,4250.24 4237.3,4250.24 4249.1,4238.44 4295.49,4238.44 v1(4297.3,4240.24)
IO3: CN8.21 U1.15 | length 716.4
  Top Layer w10: v2(3995.67,3525.22) 4048.48,3525.22 4081.6,3558.34 4081.6,3604.54 4173.4,3696.35 CN8.21
IO4: CN8.30 U1.4 | length 1352.5
  Top Layer w10: v1(3442.3,3410.24) 3447.3,3415.24 v2(3447.3,3455.24) 3448.92,3456.86 U1.4 ; v1(4302.3,3515.24) 4307.3,3520.24 4613.01,3520.24 CN8.30
  Bottom Layer w10: v1(3442.3,3410.24) 3451.44,3410.24 3543.44,3318.23 4119.43,3318.23 4302.3,3501.09 v1(4302.3,3515.24)
IO5: CN8.29 U1.5 | length 1293.8
  Top Layer w10: v1(3497.3,3405.24) v2(3497.3,3456.1) U1.5 ; v1(4267.3,3525.24) 4280.93,3538.87 CN8.29
  Bottom Layer w10: v1(3497.3,3405.24) 3562.3,3340.24 4107.3,3340.24 4267.3,3500.24 v1(4267.3,3525.24)
IO6: CN8.28 U1.6 | length 1248.3
  Top Layer w10: v1(3547.3,3405.24) v2(3547.3,3456.1) U1.6 ; v1(4227.3,3525.24) 4260.6,3558.55 CN8.28
  Bottom Layer w10: v1(3547.3,3405.24) 3597.3,3355.24 4097.3,3355.24 4227.3,3485.24 v1(4227.3,3525.24)
IO7: CN8.27 U1.7 | length 1204.5
  Top Layer w10: v1(3597.3,3405.24) v2(3597.3,3456.1) U1.7 ; v1(4217.3,3560.24) 4237.3,3580.24 4612.07,3580.24 CN8.27
  Bottom Layer w10: v1(3597.3,3405.24) 3632.3,3370.24 4082.3,3370.24 4202.3,3490.24 4202.3,3545.24 v1(4217.3,3560.24)
IO8: CN8.22 U1.12 | length 1036.9
  Top Layer w10: v2(3848.92,3457.72) 3848.92,3411.35 3890.03,3370.24 3977.3,3370.24 4007.3,3400.24 4042.3,3400.24 4100.88,3458.82 4100.88,3593.82 4186.52,3679.46 4611.27,3679.46 CN8.22
IO9: CN8.20 U1.17 | length 656
  Top Layer w10: v2(3995.67,3625.22) 4052.28,3625.22 4143.09,3716.03 CN8.20
IO10: CN8.19 U1.18 | length 643.5
  Top Layer w10: v2(3995.67,3675.22) 4000.69,3680.24 4057.3,3680.24 4112.77,3735.72 CN8.19
IO11: CN8.18 U1.19 | length 630.9
  Top Layer w10: v2(3995.67,3725.22) 4000.69,3730.24 4072.3,3730.24 4097.45,3755.4 CN8.18
IO12: CN8.17 U1.20 | length 618.5
  Top Layer w10: U1.20 v2(3995.8,3775.09) CN8.17
IO13: CN8.16 U1.21 | length 631
  Top Layer w10: v2(3995.67,3825.22) 4402.3,3825.24 4432.3,3795.24 4613.6,3795.24 CN8.16
IO14: CN8.15 U1.22 | length 643.6
  Top Layer w10: v2(3995.67,3875.22) 4377.04,3875.22 4437.8,3814.46 CN8.15
IO15: CN8.26 U1.8 | length 1272.3
  Top Layer w10: v2(3648.92,3457.72) 3648.92,3405.24 3753.92,3300.24 4064.61,3300.24 4179.01,3414.63 4179.01,3564.63 4212.3,3597.92 CN8.26
IO16: CN8.25 U1.9 | length 1216.6
  Top Layer w10: v2(3698.92,3457.72) 3698.92,3411.35 3795.03,3315.24 4047.3,3315.24 4161.2,3429.14 4161.2,3579.14 4202.3,3620.24 4611.44,3620.24 CN8.25
IO17: CN8.24 U1.10 | length 1173.4
  Top Layer w10: U1.10 3748.92,3458.62 v2(3747.3,3460.24) 3747.3,3405.24 3817.3,3335.24 4045.24,3335.24 4142.3,3432.29 4142.3,3589.28 4193.1,3640.09 4611.27,3640.09 CN8.24
IO18: CN8.23 U1.11 | length 1107
  Top Layer w10: v2(3798.92,3457.72) 3798.92,3411.35 3860.03,3350.24 4032.3,3350.24 4121.25,3439.19 4121.25,3594.19 4186.83,3659.77 4611.28,3659.77 CN8.23
IO21: CN8.14 U1.23 | length 656.1
  Top Layer w10: v2(3995.67,3925.22) 4352.04,3925.22 4443.12,3834.14 CN8.14
IO35: CN8.10 U1.28 | length 889.3
  Top Layer w10: v2(3898.92,4142.76) 3898.92,4189.13 3915.03,4205.24 4077.3,4205.24 4158.3,4124.24 4233.3,4124.24 4444.65,3912.88 CN8.10
IO36: CN8.9 U1.29 | length 936.4
  Top Layer w10: v2(3848.92,4142.76) 3848.92,4176.86 3892.3,4220.24 4082.3,4220.24 4164.3,4138.24 4239.9,4138.24 4445.58,3932.56 CN8.9
IO37: CN8.8 U1.30 | length 1005.3
  Top Layer w10: v2(3798.92,4142.76) 3798.92,4201.86 3832.3,4235.24 4087.3,4235.24 4170.3,4152.24 4245.7,4152.24 4445.69,3952.25 CN8.8
IO38: CN8.7 U1.31 | length 1071.3
  Top Layer w10: v2(3748.92,4142.76) 3748.92,4221.86 3777.3,4250.24 4092.5,4250.24 4176.5,4166.24 4251.5,4166.24 4445.81,3971.93 CN8.7
IO39: CN8.6 U1.32 | length 1131.4
  Top Layer w10: v2(3698.92,4142.76) 3698.92,4231.86 3732.3,4265.24 4097.3,4265.24 4182.3,4180.24 4257.3,4180.24 4445.91,3991.62 CN8.6
IO40: CN8.5 U1.33 | length 1101.3
  Top Layer w10: v2(3648.92,4142.76) v1(3648.92,4195.24) ; v1(4322.3,4165.24) 4476.23,4011.3 CN8.5
  Bottom Layer w10: v1(3648.92,4195.24) 3657.93,4204.25 4213.49,4204.25 4252.51,4165.24 v1(4322.3,4165.24)
IO41: CN8.4 U1.34 | length 1126.7
  Top Layer w10: v2(3598.92,4142.76) 3602.3,4146.14 v1(3602.3,4195.24) ; v1(4292.3,4190.24) 4367.3,4190.24 4527.3,4030.24 4577.3,4030.24
  Bottom Layer w10: v1(3602.3,4195.24) 3602.3,4210.23 3612.3,4220.24 4217.3,4220.24 4237.3,4200.24 4282.3,4200.24 v1(4292.3,4190.24)
IO42: CN8.3 U1.35 | length 1214.5
  Top Layer w10: v2(3548.92,4142.76) v1(3548.92,4195.24) ; v1(4317.3,4215.24) 4367.3,4215.24 4531.86,4050.67 CN8.3
  Bottom Layer w10: v1(3548.92,4195.24) 3548.92,4201.86 3582.3,4235.24 4227.3,4235.24 4247.3,4215.24 v1(4317.3,4215.24)
IO45: CN8.11 U1.26 | length 696.1
  Top Layer w10: U1.26 4262.49,4075.22 4447.31,3890.4 4611.28,3890.4 CN8.11
  other v2: 3995.55,4072.78
IO46: U1.16
  other v2: 3995.67,3575.22
IO47: CN8.13 U1.24 | length 668.7
  Top Layer w10: v2(3995.67,3975.22) 4322.87,3975.22 4444.26,3853.83 CN8.13
IO48: CN8.12 U1.25 | length 683
  Top Layer w10: U1.25 4292.67,4025.22 4446.51,3871.38 4611.94,3871.38 CN8.12
  other v2: 3995.55,4022.78
LEDCAP: CN7.7 RN3.4 U2.21 | length 1261.2
  Top Layer w10: CN7.7 6008.98,3463.55 v1(6022.3,3450.24) ; v1(6382.3,3370.24) 6382.73,3370.67 RN3.4 ; U2.21 6459.11,3962.24 6515.29,3962.24 v1(6517.3,3960.24)
  Bottom Layer w10: v1(6022.3,3450.24) 6022.3,3420.24 6072.3,3370.24 v1(6382.3,3370.24) 6382.3,3915.24 6427.3,3960.24 v1(6517.3,3960.24)
RTS: Q1.2 R9.1 U3.13 | length 1067
  Top Layer w10: U3.13 3340,4430.24 3317.3,4430.24 3307.3,4440.24 3307.3,4485.24 3327.3,4505.24 3873.34,4505.24 3967.57,4411.01 R9.1 3983.84,4410.24 4012.3,4410.24 4022.3,4400.24 4022.3,4340.24 4042.3,4320.24 4119.06,4320.24 4134.69,4335.87 Q1.2
TPCLK: CN7.9 RN3.2 U2.39 | length 1280.1
  Top Layer w10: CN7.9 6019.98,3502.92 v1(6037.3,3520.24) ; v1(6312.3,3485.24) 6422.3,3485.24 6448.05,3459.49 v1(6448.05,3370.67) ; U2.39 6515.28,3783.22 v1(6517.3,3785.24)
  Bottom Layer w10: v1(6037.3,3520.24) 6057.3,3520.24 6092.3,3485.24 v1(6312.3,3485.24) ; v1(6448.05,3370.67) 6448.05,3350.24 6458.05,3340.24 6492.53,3340.24 6502.53,3350.24 6502.53,3510 6447.3,3565.24 6447.3,3750.24 6482.3,3785.24 v1(6517.3,3785.24)
TPDATA: CN7.10 RN3.1 U2.37 | length 1208
  Top Layer w10: CN7.10 5982.95,3522.6 6017.3,3556.94 v1(6017.3,3560.24) ; v1(6312.3,3515.24) 6442.3,3515.24 v1(6479.53,3478) RN3.1 ; U2.37 6493.41,3802.9 6510.75,3820.24 v1(6517.3,3820.24)
  Bottom Layer w10: v1(6017.3,3560.24) 6062.3,3560.24 6107.3,3515.24 v1(6312.3,3515.24) ; v1(6479.53,3478) 6479.53,3503 6422.3,3560.24 6422.3,3789.38 6453.15,3820.24 v1(6517.3,3820.24)
TPREST: C7.2 CN7.8 R10.1 U2.40 | length 1060.2
  Top Layer w10: CN7.8 6048.97,3483.23 6122.3,3409.9 R10.1 6169.4,3359.9 6184.73,3375.24 C7.2 v1(6219.73,3445.24) ; v1(6192.3,3770.24) 6201.58,3779.52 6283.65,3779.52 U2.40
  Bottom Layer w10: v1(6192.3,3770.24) 6192.3,3769.38 6356.44,3605.24 6356.44,3455.24 6346.44,3445.24 v1(6219.73,3445.24)
U0RXD: U1.36 U3.4 | length 330.4
  Top Layer w10: U3.4 3427.3,4342.52 3427.3,4320.24 v1(3457.3,4290.24) ; v2(3498.92,4142.76) 3498.92,4192.76 3553.25,4247.09 3553.25,4289.28 v1(3552.3,4290.24)
  Bottom Layer w10: v1(3457.3,4290.24) v1(3552.3,4290.24)
U0TXD: U1.37 U3.5 | length 289.7
  Top Layer w10: v2(3448.92,4142.76) 3448.92,4190.24 3509.3,4250.62 3509.3,4341.05 3480.03,4370.33 U3.5
V3: C3.2 U3.6 | length 111.3
  Top Layer w10: U3.6 3506.46,4390.01 3528.15,4411.7 C3.2
VBUSB: C2.2 C4.2 CN1.4 CN5.4 CN6.4 CN8.32 U3.3 U3.9 U4.3 | length 2495
  Top Layer w10: v1(3307.3,4275.24) 3317.3,4265.24 3390.32,4265.24 3407.85,4282.77 U3.3 ; C2.2@3692.3,4426.7 v1(3692.3,4460.24) ; v1(4407.3,3465.24) 4448.1,3424.44 4516.49,3424.44 4569.07,3477.02 4611.28,3477.02 CN8.32 ; U4.3 4511.74,4485.79 v1(4512.3,4485.24) ; v1(4694.74,4603.47) 4747.3,4550.92 C4.2
  Bottom Layer w10: v1(3307.3,4275.24) 3292.3,4290.24 3292.3,4425.24 3322.3,4455.24 3442.3,4455.24 v1(3452.3,4465.24) ; 3552.3,4590.24 v1(3582.03,4590.24) v1(3622.41,4590.24) 3672.3,4590.24 3692.3,4570.24 v1(3692.3,4460.24) ; v1(4407.3,3465.24) 4407.3,4090.24 4432.3,4115.24 4432.3,4450.24 4467.3,4485.24 v1(4512.3,4485.24) 4552.3,4485.24 4617.3,4550.24 4652.3,4550.24 4652.3,4585.24 v1(4662.3,4595.24)
  other v1: 4132.3,4590.24 4093.35,4592.24
VBUSB1: CN2.4 USB2.A4B9 USB2.B4A9 | length 92.1
  Top Layer w10: v1(3772.3,5805.24) 3777.81,5810.75 USB2.B4A9 ; USB2.A4B9 3966.78,5800.75 v1(3967.3,5800.24)
  other v1: 3762.3,5700.24 3762.3,5730.24
VBUSB2: CN3.4 USB_DEBUG1.A4B9 USB_DEBUG1.B4A9 | length 74.6
  Top Layer w10: v1(4847.81,5815.24) USB_DEBUG1.B4A9 ; v1(5036.78,5815.24) USB_DEBUG1.A4B9
  other v1: 4837.3,5685.24 4837.3,5718.59
VCC5V_11: C7.1 C8.2 CN7.3 RN1.5 RN1.6 RN1.7 RN1.8 RN2.5 RN2.6 RN2.7 RN2.8 RN3.5 RN3.6 RN3.7 RN3.8 U2.35 U2.38 | length 2672.1
  Top Layer w10: RN2.8 RN2.7 RN2.6 5843.48,4270.24 v1(5877.3,4270.24) ; CN7.3@5960.52,3385.12 6027.7,3385.12 6057.82,3415.24 v1(6067.3,3415.24) ; v1(6087.3,3590.24) 6087.3,3572.56 RN1.5 ; v1(6137.3,3445.24) 6137.3,3517.04 RN1.5 ; v1(6212.3,3835.24) 6212.3,3832.95 6242.35,3802.9 U2.38 ; U2.35 6478.3,3822.59 6507.74,3852.04 6527.3,3852.04 6542.3,3837.04 6542.3,3770.24 6522.3,3750.24 6522.3,3340.24 6519.97,3340.24 RN3.8 RN3.7 RN3.6 RN3.5 6384.62,3300.24 6274.85,3300.24 C7.1 6274.85,3479.48 RN1.8 RN1.7 RN1.6 RN1.5
  Bottom Layer w10: v1(5877.3,4270.24) 5952.3,4195.24 5952.3,4025.24 6022.3,4025.24 v1(6212.3,3835.24) 6087.3,3710.24 v1(6087.3,3590.24) ; v1(6067.3,3415.24) 6107.3,3415.24 v1(6137.3,3445.24)
VDD33: C1.1 C5.2 CN8.31 R1.1 R3.2 U1.2 U3.1 U4.2 U4.4 | length 4723.2
  Top Layer w10: R3.2 3310.26,3358.22 v1(3348.92,3396.88) v2(3348.92,3457.72) ; U3.1 3367.25,4341.54 3367.25,4315.24 3352.25,4300.24 3327.3,4300.24 3287.3,4340.24 3287.3,4495.24 3313.91,4521.85 3713.94,4521.85 ; v1(3587.3,4460.24) 3622.3,4460.24 C1.1@3622.3,4426.7 ; v1(3627.3,4550.24) 3685.55,4550.24 3713.94,4521.85 ; v1(4362.3,3490.24) v1(4492.3,3490.24) 4532.3,3490.24 4541.56,3499.5 CN8.31 ; v1(4619.6,4250.24) 4577.3,4292.54 4577.3,4345.24 4528.9,4345.24 4508.9,4365.24 U4.2 ; R1.1 4602.3,4497.28 4588.3,4483.28 4588.3,4410.48 4573.05,4395.24 U4.2 ; 3713.94,4521.85 3714.34,4522.24 3876.13,4522.24 3946.8,4451.57 4043.63,4451.57 4080.29,4488.23 4131.79,4488.23 4224.78,4395.24 U4.4 U4.2
  Bottom Layer w10: v1(3348.92,3396.88) 3348.92,3363.62 3437.3,3275.24 4147.3,3275.24 v1(4362.3,3490.24) ; v1(3587.3,4460.24) 3587.3,4510.24 v1(3627.3,4550.24) ; v1(4492.3,3490.24) 4492.3,4185.24 4557.3,4250.24 v1(4619.6,4250.24)
VDD33_11: CN7.4
"": CN1.5 CN1.6 CN2.5 CN2.6 CN3.5 CN3.6 CN5.5 CN5.6 CN6.5 CN6.6 CN7.5 CN7.35 CN7.36 CN8.35 CN8.36 CN9.5 CN9.6 pad.1 U2.19 U2.23 U2.25 U2.27 U2.29 U2.33 U2.34 U2.36 U3.10 U3.11 U3.14 U3.15 U3.16 USB2.A8 USB2.B8 USB_DEBUG1.A8 USB_DEBUG1.B8

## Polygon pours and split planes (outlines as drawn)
GND_USB on Bottom Layer (solid, remove dead copper, pour order 0): 3657.3,5540.24 4087.3,5540.24 4087.3,6110.24 3657.3,6110.24
GND_USB on Top Layer (solid, remove dead copper, pour order 1): 3662.3,5535.24 4092.3,5535.24 4092.3,6110.24 3662.3,6110.24
GND_DEBUG on Top Layer (solid, remove dead copper, pour order 2): 4727.3,5525.24 5152.3,5525.24 5152.3,6110.24 4727.3,6110.24
GND_DEBUG on Bottom Layer (solid, remove dead copper, pour order 3): 4727.3,5524.95 5151.55,5524.95 5151.55,6110.24 4727.3,6110.24
GND_11 on Bottom Layer (solid, remove dead copper, pour order 6): 5737.3,3195.24 6582.3,3195.24 6582.3,4390.24 5737.3,4390.24
GND on Bottom Layer (solid, remove dead copper, pour order 4): 3242.3,4825.24 3255.73,4825.24 3255.73,4830.24 3247.3,4830.24
GND on Bottom Layer (solid, remove dead copper, pour order 5): 3255.73,4830.24 4805.01,4830.24 4805.01,3215.24 3252.3,3215.24 3257.3,3407.6 4049.66,3407.6 4049.66,4183.81 4056.09,4190.24 3282.35,4190.24 3255.73,4216.86

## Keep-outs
Board Outline Layer:
  lines w10 net "": 3119.18,3000 6819.97,3000 6819.97,6307.09 3119.18,6307.09 3119.18,3000

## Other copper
Top Layer:
  region net VBUSB2: 4807.3,5665.24 4892.3,5665.24 4892.3,5740.24 4807.3,5740.24
  region net VBUSB: 3542.3,4575.24 3642.3,4575.24 3642.3,4620.24 3542.3,4620.24
  region net VBUSB: 4087.3,4575.24 4157.3,4575.24 4157.3,4620.24 4087.3,4620.24
  region net VBUSB: 4647.3,4575.24 4712.3,4575.24 4712.3,4631.71 4647.3,4631.71
  region net VBUSB1: 3822.3,5685.24 3822.3,5745.24 3737.3,5745.24 3737.3,5685.24
  region net VBUSB: 3422.3,4480.24 3477.3,4480.24 3477.3,4455.24 3462.3,4441.9 3436.85,4442.17 3422.3,4442.17
Bottom Layer:
  region net VBUSB1: 3786.21,5685.24 3787.3,5775.24 3807.3,5805.24 3942.3,5805.24 3957.3,5775.24 4002.3,5775.24 4000.54,5870.24 3742.3,5870.24 3742.3,5685.24
  region net VBUSB2: 4832.3,5880.24 5052.3,5880.24 5052.3,5795.24 5022.3,5795.24 5018.53,5825.24 4876.79,5825.24 4873.4,5821.85 4873.4,5666.79 4871.85,5665.24 4807.3,5665.24 4807.3,5770.24 4832.3,5800.24
  region net VBUSB: 4707.3,4575.24 4707.3,4620.24 3487.3,4620.24 3447.3,4565.24 3442.3,4495.24 3422.3,4480.24 3424.89,4440.24 3457.3,4440.24 3477.3,4455.24 3472.3,4545.24 3502.3,4575.24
